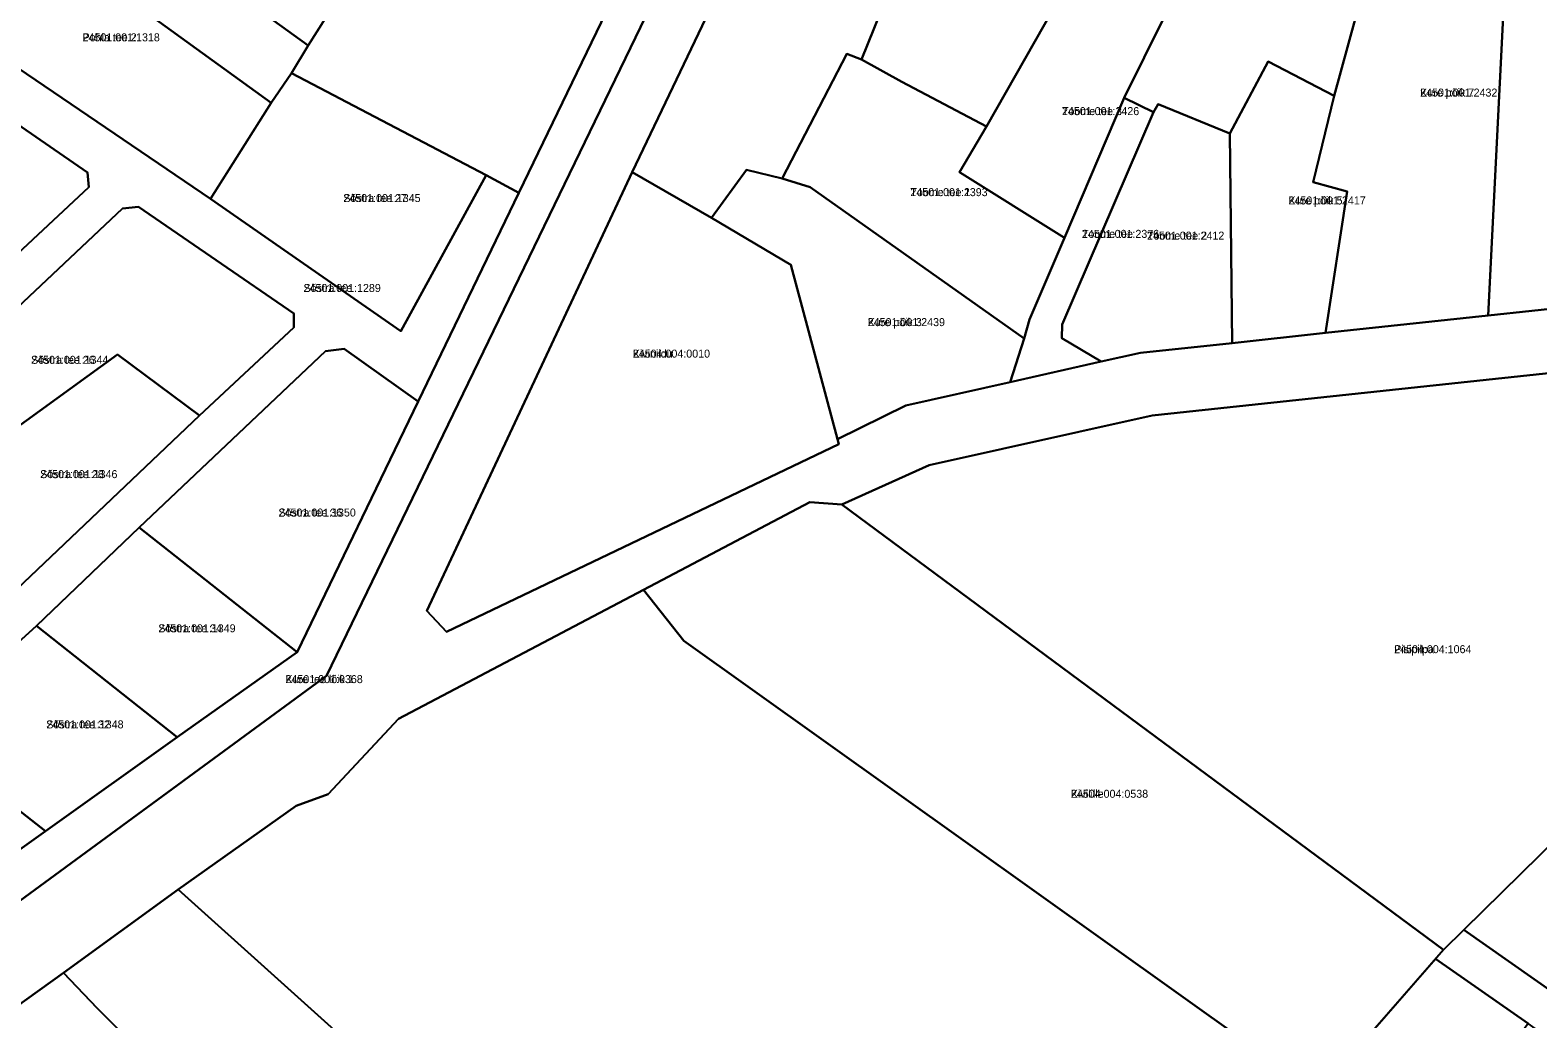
# Model space of a CAD drawing. Extents: x 551291 to 575799, y 6581704 to 6610137.
# Drawn here: x 559243.4 to 559526.5, y 6593771.7 to 6593957.3 of the extents above; entities that cross this region are included whole.
import ezdxf

# ---------------------------------------------------------------- set-up
doc = ezdxf.new("R2010")
doc.units = 0
for name, color, linetype in [('L_AADRESS', 7, 'Continuous'), ('PIIR', 7, 'Continuous'), ('TUNNUS', 7, 'Continuous')]:
    doc.layers.add(name, color=color, linetype=linetype)

msp = doc.modelspace()

# ---------------------------------------------------------------- linework, layer by layer
at = {"layer": 'PIIR'}
for points in [[(558177.52, 6592770.55), (558170.99, 6592891.67), (558187.73, 6592959.33), (558210.3, 6593010.98), (558251.88, 6593067.47), (558331.23, 6593148.23), (558500.98, 6593273.8), (558515.98, 6593265.59), (558725.44, 6593417.8), (558892.15, 6593539.14), (558974.44, 6593599.03), (559131.4, 6593713.23), (559146.17, 6593723.99), (559299.06, 6593836.09), (559444.58, 6594136.67), (559447.22, 6594142.1), (559464.89, 6594178.58), (559481.53, 6594212.94), (559484.05, 6594218.05)], [(559492.26, 6594213.33), (559480.81, 6594189.47), (559468.99, 6594164.84), (559453.77, 6594133.23), (559441.92, 6594108.7), (559431.33, 6594086.6), (559425.5, 6594074.54), (559399.64, 6594020.83), (559383.45, 6593987.17), (559356.41, 6593930.63), (559317.89, 6593848.3), (559321.54, 6593844.35), (559395.22, 6593879.55), (559395, 6593880.5), (559407.84, 6593886.81), (559427.42, 6593891.23), (559444.52, 6593895.06), (559451.86, 6593896.71), (559469.1, 6593898.55), (559486.64, 6593900.44), (559517.17, 6593903.73), (559533.53, 6593905.49)], [(559216.48, 6593966.93), (559277.28, 6593925.6), (559313.02, 6593900.79), (559329.03, 6593930.04), (559335.18, 6593926.77), (559316.24, 6593887.55), (559302.36, 6593897.43), (559298.83, 6593897.03), (559263.84, 6593863.92), (559244.59, 6593845.49), (559237.57, 6593839.14)], [(559218.03, 6593893.87), (559254.43, 6593927.81), (559254.15, 6593930.55), (559217.11, 6593956.06)], [(559238.38, 6593849.98), (559275.2, 6593884.95), (559292.93, 6593901.44), (559292.88, 6593904.11), (559263.77, 6593924.11), (559260.76, 6593923.79), (559223.41, 6593888.67)], [(559547.24, 6593894.87), (559454.05, 6593884.92), (559412.21, 6593875.63), (559395.77, 6593868.26), (559389.79, 6593868.69), (559358.56, 6593852.25), (559312.56, 6593828.02), (559299.35, 6593813.89), (559293.37, 6593811.67), (559271.2, 6593795.97), (559249.66, 6593780.34), (559228.92, 6593765.5)], [(559550.37, 6593752.51), (559524.69, 6593770.84), (559507.27, 6593782.93), (559508.79, 6593784.67), (559512.57, 6593788.38), (559534.19, 6593773.28)]]:
    msp.add_lwpolyline(points, dxfattribs=at)
for points in [[(559171.21, 6593753.59), (559201.87, 6593775.34), (559209.55, 6593780.73), (559246.25, 6593806.94), (559271.02, 6593824.58), (559293.51, 6593840.52), (559316.24, 6593887.55), (559335.18, 6593926.77), (559358.82, 6593975.74), (559369.18, 6593996.97), (559372.27, 6594003.33), (559388.13, 6594036.07), (559408, 6594077.05), (559411.94, 6594085.21), (559438.12, 6594139.38), (559444.58, 6594136.67), (559299.06, 6593836.09), (559146.17, 6593723.99), (559138.1, 6593729.93)], [(559295.57, 6593954.38), (559240.57, 6593994.11), (559249.43, 6594003.75), (559302.54, 6593965.43)], [(559329.03, 6593930.04), (559292.49, 6593949.23), (559295.57, 6593954.38), (559302.54, 6593965.43), (559309.71, 6593976.78), (559316.9, 6593987.46), (559321.68, 6593995.94), (559340.62, 6593985.59), (559358.82, 6593975.74), (559335.18, 6593926.77)], [(559288.65, 6593943.64), (559231.85, 6593984.75), (559240.57, 6593994.11), (559295.57, 6593954.38), (559292.49, 6593949.23)], [(559453.74, 6593982.85), (559458.39, 6593990.56), (559483.44, 6593986.78), (559487.09, 6593984.93), (559477.21, 6593965.41), (559492.2, 6593959.32), (559488.25, 6593944.93), (559475.84, 6593951.42), (559468.67, 6593937.86), (559455.2, 6593943.41), (559454.33, 6593941.91), (559448.82, 6593944.59), (559456.34, 6593959.73), (559463.21, 6593973.42)], [(559356.41, 6593930.63), (559383.45, 6593987.17), (559409.15, 6593975.66), (559399.46, 6593951.77), (559396.72, 6593952.85), (559384.6, 6593929.42), (559377.88, 6593931.06), (559371.31, 6593922.02)], [(559484.28, 6593928.76), (559488.25, 6593944.93), (559492.2, 6593959.32), (559503.91, 6593987.47), (559510.5, 6593984.68), (559524.48, 6593978.3), (559522.99, 6593974.73), (559520.38, 6593968.65), (559517.17, 6593903.73), (559486.64, 6593900.44), (559490.65, 6593927.02)], [(559216.48, 6593966.93), (559216.33, 6593968.06), (559231.85, 6593984.75), (559288.65, 6593943.64), (559277.28, 6593925.6)], [(559409.15, 6593975.66), (559411.9, 6593982.1), (559419.69, 6593977.74), (559425.04, 6593974.79), (559439.32, 6593967.96), (559422.99, 6593939.22), (559407.09, 6593947.55), (559399.46, 6593951.77)], [(559422.99, 6593939.22), (559439.32, 6593967.96), (559456.34, 6593959.73), (559448.82, 6593944.59), (559437.59, 6593918.27), (559417.92, 6593930.65)], [(559517.17, 6593903.73), (559520.38, 6593968.65), (559547.7, 6593962.42), (559544.62, 6593948.45), (559541.76, 6593948.19), (559533.53, 6593905.49)], [(559208.87, 6593912.05), (559189.1, 6593929.66), (559215.23, 6593955.78), (559217.11, 6593956.06), (559254.15, 6593930.55), (559254.43, 6593927.81), (559218.03, 6593893.87), (559203.42, 6593906.86)], [(559384.6, 6593929.42), (559396.72, 6593952.85), (559399.46, 6593951.77), (559407.09, 6593947.55), (559422.99, 6593939.22), (559417.92, 6593930.65), (559437.59, 6593918.27), (559431.04, 6593902.96), (559430.01, 6593899.39), (559389.84, 6593927.81)], [(559469.1, 6593898.55), (559468.67, 6593937.86), (559475.84, 6593951.42), (559488.25, 6593944.93), (559484.28, 6593928.76), (559490.65, 6593927.02), (559486.64, 6593900.44)], [(559313.02, 6593900.79), (559277.28, 6593925.6), (559288.65, 6593943.64), (559292.49, 6593949.23), (559329.03, 6593930.04)], [(559444.52, 6593895.06), (559427.42, 6593891.23), (559430.01, 6593899.39), (559431.04, 6593902.96), (559437.59, 6593918.27), (559448.82, 6593944.59), (559454.33, 6593941.91), (559437.18, 6593902.01), (559437.12, 6593899.45)], [(559437.18, 6593902.01), (559454.33, 6593941.91), (559455.2, 6593943.41), (559468.67, 6593937.86), (559469.1, 6593898.55), (559451.86, 6593896.71), (559444.52, 6593895.06), (559437.12, 6593899.45)], [(559386.21, 6593913.24), (559395, 6593880.5), (559395.22, 6593879.55), (559321.54, 6593844.35), (559317.89, 6593848.3), (559356.41, 6593930.63), (559371.31, 6593922.02)], [(559386.21, 6593913.24), (559371.31, 6593922.02), (559377.88, 6593931.06), (559384.6, 6593929.42), (559389.84, 6593927.81), (559430.01, 6593899.39), (559427.42, 6593891.23), (559407.84, 6593886.81), (559395, 6593880.5)], [(559216.68, 6593865.19), (559207.9, 6593871.33), (559223.41, 6593888.67), (559260.76, 6593923.79), (559263.77, 6593924.11), (559292.88, 6593904.11), (559292.93, 6593901.44), (559275.2, 6593884.95), (559259.81, 6593896.4)], [(559221.9, 6593861.59), (559216.68, 6593865.19), (559259.81, 6593896.4), (559275.2, 6593884.95), (559238.38, 6593849.98)], [(559293.51, 6593840.52), (559263.84, 6593863.92), (559298.83, 6593897.03), (559302.36, 6593897.43), (559316.24, 6593887.55)], [(559395.77, 6593868.26), (559412.21, 6593875.63), (559454.05, 6593884.92), (559547.24, 6593894.87), (559575.36, 6593895.99), (559620.01, 6593893.86), (559561.4, 6593836.32), (559555.99, 6593831.01), (559537.65, 6593813), (559512.57, 6593788.38), (559508.79, 6593784.67)], [(559358.56, 6593852.25), (559389.79, 6593868.69), (559395.77, 6593868.26), (559508.79, 6593784.67), (559485.21, 6593757.68), (559366.12, 6593842.62)], [(559271.02, 6593824.58), (559244.59, 6593845.49), (559263.84, 6593863.92), (559293.51, 6593840.52)], [(559400.41, 6593682.53), (559398.02, 6593680.52), (559392.78, 6593685.23), (559372.46, 6593703.92), (559362.29, 6593713.22), (559353.5, 6593721.24), (559344.69, 6593729.33), (559331.38, 6593741.49), (559309.88, 6593761.17), (559271.2, 6593795.97), (559293.37, 6593811.67), (559299.35, 6593813.89), (559312.56, 6593828.02), (559358.56, 6593852.25), (559366.12, 6593842.62), (559485.21, 6593757.68), (559465.82, 6593735.48), (559464.42, 6593733.88), (559460.32, 6593730.35), (559434.91, 6593708.44), (559433.03, 6593707.03), (559426.01, 6593701.76), (559420.53, 6593697.64), (559406.41, 6593687.04)], [(559246.25, 6593806.94), (559222.88, 6593825.25), (559237.57, 6593839.14), (559244.59, 6593845.49), (559271.02, 6593824.58)], [(559209.55, 6593780.73), (559186.62, 6593798.55), (559218.47, 6593828.73), (559222.88, 6593825.25), (559246.25, 6593806.94)], [(559534.19, 6593773.28), (559512.57, 6593788.38), (559537.65, 6593813), (559554.76, 6593800.66)], [(559249.66, 6593780.34), (559271.2, 6593795.97), (559309.88, 6593761.17), (559286.68, 6593743.26), (559277.59, 6593752.86), (559271.93, 6593758.09), (559264.37, 6593765.3), (559260.03, 6593769.65), (559256, 6593773.68)], [(559228.92, 6593765.5), (559249.66, 6593780.34), (559256, 6593773.68), (559260.03, 6593769.65), (559238.81, 6593754.43), (559235.7, 6593757.89)], [(559504.42, 6593743.87), (559485.21, 6593757.68), (559507.27, 6593782.93), (559524.69, 6593770.84)]]:
    msp.add_lwpolyline(points, close=True, dxfattribs=at)

# ---------------------------------------------------------------- texts
at = {"layer": 'L_AADRESS'}
for s, p in [('Pohla tee 2', (559253.24, 6593955.18)), ('Kure põik 7', (559504.38, 6593944.81)), ('Toome tee 3', (559437.13, 6593941.33)), ('Toome tee 1', (559408.67, 6593926.12)), ('Sõstra tee 27', (559302.2, 6593925.01)), ('Kure põik 5', (559479.66, 6593924.56)), ('Toome tee', (559440.88, 6593918.29)), ('Toome tee 2', (559453.11, 6593917.96)), ('Sõstra tee', (559294.73, 6593908.13)), ('Kure põik 3', (559400.66, 6593901.72)), ('Kiviniidu', (559356.55, 6593895.81)), ('Sõstra tee 26', (559243.58, 6593894.65)), ('Sõstra tee 28', (559245.28, 6593873.19)), ('Sõstra tee 36', (559290.04, 6593865.98)), ('Sõstra tee 34', (559267.47, 6593844.25)), ('Pisipilpa', (559499.51, 6593840.33)), ('Kure tee lõik 1', (559291.34, 6593834.71)), ('Sõstra tee 32', (559246.43, 6593826.21)), ('Kivilille', (559438.81, 6593813.19))]:
    msp.add_text(s, height=1.5, dxfattribs=at).set_placement(p)
at = {"layer": 'TUNNUS'}
for s, p in [('24501:001:1318', (559253.24, 6593955.18)), ('24501:001:2432', (559504.38, 6593944.81)), ('24501:001:2426', (559437.13, 6593941.33)), ('24501:001:2393', (559408.67, 6593926.12)), ('24501:001:1345', (559302.2, 6593925.01)), ('24501:001:2417', (559479.66, 6593924.56)), ('24501:001:2376', (559440.88, 6593918.29)), ('24501:001:2412', (559453.11, 6593917.96)), ('24501:001:1289', (559294.73, 6593908.13)), ('24501:001:2439', (559400.66, 6593901.72)), ('24504:004:0010', (559356.55, 6593895.81)), ('24501:001:1344', (559243.58, 6593894.65)), ('24501:001:1346', (559245.28, 6593873.19)), ('24501:001:1350', (559290.04, 6593865.98)), ('24501:001:1349', (559267.47, 6593844.25)), ('24504:004:1064', (559499.51, 6593840.33)), ('24501:001:0368', (559291.34, 6593834.71)), ('24501:001:1348', (559246.43, 6593826.21)), ('24504:004:0538', (559438.81, 6593813.19))]:
    msp.add_text(s, height=1.5, dxfattribs=at).set_placement(p)

doc.saveas('drawing.dxf')
